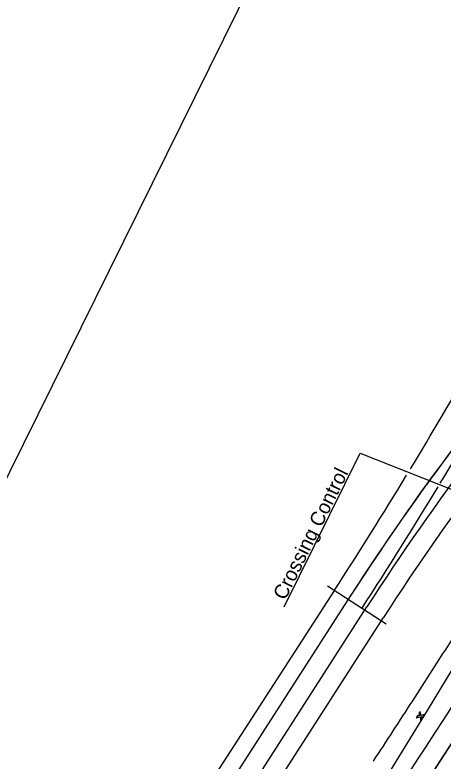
# Model space of a CAD drawing. Extents: x 14097936 to 14128734, y 8632000 to 8683104.
# Drawn here: x 14119230.8 to 14119491.1, y 8669393 to 8669846.7 of the extents above; entities that cross this region are included whole.
import ezdxf

# ---------------------------------------------------------------- set-up
doc = ezdxf.new("R2010")
doc.units = 0
for name, color, linetype in [('Cell', 7, 'Continuous'), ('dsnNonPlotable', 7, 'Continuous'), ('dsnPaintExistingChannelizingLaneWhite', 7, 'Continuous'), ('dsnPaintExistingDoubleCenterYellow', 7, 'Continuous'), ('dsnPaintPlaceDoubleCenterLineYellow', 7, 'Continuous'), ('dsnPavementRmvl', 7, 'Continuous'), ('dsnShadingPaved', 7, 'Continuous'), ('dsnStdLabel', 7, 'Continuous'), ('dsnStgShadingPropPav', 7, 'Continuous'), ('dsnTapePlaceChannelizingLaneWhite', 7, 'Continuous'), ('dsnTextOverlapEven', 7, 'Continuous')]:
    doc.layers.add(name, color=color, linetype=linetype)

msp = doc.modelspace()

# ---------------------------------------------------------------- linework, layer by layer
at = {"layer": 'Cell'}
for p, q in [((14119475.53, 8669420.45), (14119474.8, 8669419.29)), ((14119474.8, 8669419.29), (14119477.12, 8669419.82)), ((14119476.95, 8669420.59), (14119475.53, 8669420.45)), ((14119477.2, 8669423.1), (14119476.47, 8669421.93)), ((14119476.47, 8669421.93), (14119476.95, 8669420.59)), ((14119477.12, 8669419.82), (14119477.65, 8669417.49)), ((14119477.73, 8669420.77), (14119477.2, 8669423.1)), ((14119480.05, 8669421.29), (14119477.73, 8669420.77)), ((14119477.9, 8669419.99), (14119479.32, 8669420.13)), ((14119478.38, 8669418.65), (14119477.9, 8669419.99)), ((14119479.32, 8669420.13), (14119480.05, 8669421.29)), ((14119477.65, 8669417.49), (14119478.38, 8669418.65))]:
    msp.add_line(p, q, dxfattribs=at)
at = {"layer": 'dsnNonPlotable'}
msp.add_lwpolyline([(14119315.27, 8668607.09), (14120010, 8670012.23), (14119557.31, 8670236.05), (14118862.58, 8668830.91)], close=True, dxfattribs=at)
at = {"layer": 'dsnPaintExistingChannelizingLaneWhite'}
for p, q in [((14119434.72, 8669493.24), (14119231.48, 8669177.36)), ((14119251.66, 8669164.37), (14119454.9, 8669480.25))]:
    msp.add_line(p, q, dxfattribs=at)
for radius in [1512, 1488]:
    msp.add_arc((14120706.26, 8668675.12), radius, 138.43496, 147.24256, dxfattribs=at)
at = {"layer": 'dsnPaintExistingDoubleCenterYellow'}
msp.add_line((14119241.57, 8669170.86), (14119444.81, 8669486.75), dxfattribs=at)
msp.add_arc((14120706.26, 8668675.12), 1500, 138.43496, 147.24256, dxfattribs=at)
at = {"layer": 'dsnPaintPlaceDoubleCenterLineYellow'}
msp.add_line((14119477.17, 8669374.04), (14119517.35, 8669436.29), dxfattribs=at)
at = {"layer": 'dsnPavementRmvl'}
for p, q in [((14119434.72, 8669493.24), (14119231.48, 8669177.36)), ((14119251.66, 8669164.37), (14119454.9, 8669480.25))]:
    msp.add_line(p, q, dxfattribs=at)
for radius, start in [(1512, 137.73115), (1488, 138.43496)]:
    msp.add_arc((14120706.26, 8668675.12), radius, start, 147.24256, dxfattribs=at)
at = {"layer": 'dsnShadingPaved'}
for p, q in [((14119491.13, 8669417.73), (14119507.3, 8669442.79)), ((14119175.01, 8668905.94), (14119517.35, 8669436.29))]:
    msp.add_line(p, q, dxfattribs=at)
msp.add_lwpolyline([(14119238.52, 8669044.85), (14119265.99, 8669086.65), (14119293.47, 8669128.44), (14119320.94, 8669170.24), (14119348.3, 8669212.11), (14119375.45, 8669254.16), (14119402.36, 8669296.35), (14119429.03, 8669338.69), (14119455.46, 8669381.17), (14119481.65, 8669423.79), (14119497.35, 8669449.49)], dxfattribs=at)
for radius in [9000, 9000, 9012]:
    msp.add_arc((14111929.66, 8674298.73), radius, 325.249705, 327.157368, dxfattribs=at)
at = {"layer": 'dsnStdLabel'}
for p, q in [((14119425.08, 8669496.82), (14119303.44, 8669308.96)), ((14119420.88, 8669499.54), (14119456.56, 8669476.44))]:
    msp.add_line(p, q, dxfattribs=at)
for radius, start, end in [(2903.66, 328.79417, 331.75546), (2923.66, 328.83376, 330.44861), (2903.66, 327.07643, 328.70563), (2923.66, 327.07643, 328.78471)]:
    msp.add_arc((14116987.75, 8671075.02), radius, start, end, dxfattribs=at)
at = {"layer": 'dsnStgShadingPropPav'}
for p, q in [((14119434.72, 8669493.24), (14119231.48, 8669177.36)), ((14119251.66, 8669164.37), (14119454.9, 8669480.25)), ((14119472.64, 8669429.66), (14119488.81, 8669454.71))]:
    msp.add_line(p, q, dxfattribs=at)
for centre, radius, start, end in [((14120706.26, 8668675.12), 1512, 137.73115, 147.24256), ((14120706.26, 8668675.12), 1488, 138.43496, 147.24256), ((14117116.91, 8670980.36), 2820.2, 327.24978, 328.48633), ((14111929.66, 8674298.73), 8978, 326.878345, 327.157369)]:
    msp.add_arc(centre, radius, start, end, dxfattribs=at)
at = {"layer": 'dsnTapePlaceChannelizingLaneWhite'}
msp.add_lwpolyline([(14119238.52, 8669044.85), (14119265.99, 8669086.65), (14119293.47, 8669128.44), (14119320.94, 8669170.24), (14119348.3, 8669212.11), (14119375.45, 8669254.16), (14119402.36, 8669296.35), (14119429.03, 8669338.69), (14119455.46, 8669381.17), (14119481.65, 8669423.79), (14119497.35, 8669449.49)], dxfattribs=at)
at = {"layer": 'dsnTextOverlapEven'}
msp.add_lwpolyline([(14119394.56, 8669486.68), (14119440.77, 8669580.14), (14119544.73, 8669538.98)], dxfattribs=at)

# ---------------------------------------------------------------- texts
msp.add_text('Crossing Control', height=8.75, rotation=63.6912, dxfattribs=at).set_placement((14119395.15, 8669490.33))

doc.saveas('drawing.dxf')
